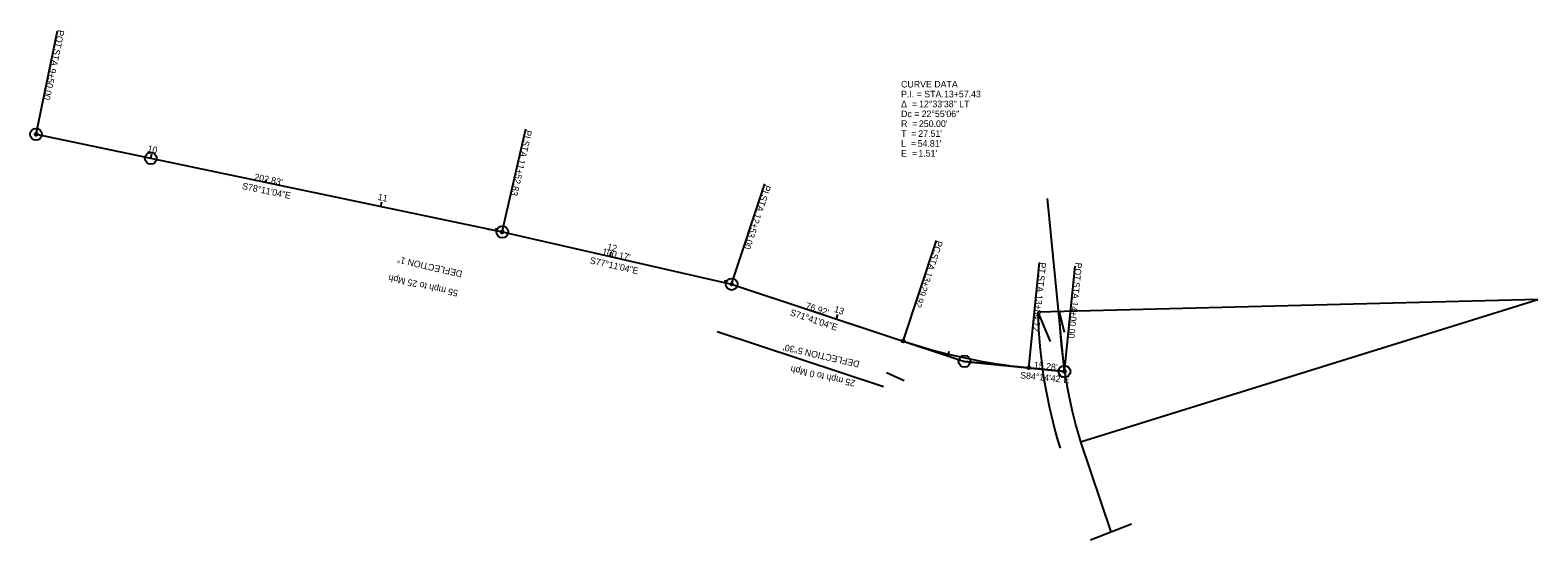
# Model space of a CAD drawing. Extents: x 1815851 to 1817341, y 427933 to 428286.
import ezdxf

# ---------------------------------------------------------------- set-up
doc = ezdxf.new("R2010")
doc.units = 0
for name, color, linetype in [('Default', 7, 'Continuous'), ('DT_P_Graded_Shoulder', 7, 'Continuous'), ('GE_P_Alignment', 7, 'Continuous'), ('GE_P_Alignment_100_Bearings', 7, 'Continuous'), ('GE_P_Alignment_100_Cardinal_Points', 7, 'Continuous'), ('GE_P_Alignment_100_Curve_Data', 7, 'Continuous'), ('GE_P_Alignment_100_Distances', 7, 'Continuous'), ('GE_P_Alignment_100_Stations', 7, 'Continuous'), ('PV_P_EOP', 7, 'Continuous'), ('SC_Scratch1', 7, 'Continuous')]:
    doc.layers.add(name, color=color, linetype=linetype)

msp = doc.modelspace()

# ---------------------------------------------------------------- linework, layer by layer
at = {"layer": 'Default'}
for p, q in [((1817139.41, 428004.77), (1817132.13, 428078.38)), ((1816893.7, 428065.42), (1816894.78, 428065.19)), ((1816900.03, 428064.1), (1816997.7, 428041.88)), ((1816997.7, 428041.88), (1817096.84, 428009.06)), ((1817340.98, 428035.36), (1817128.04, 428030)), ((1817146.28, 427974.88), (1817340.98, 428035.36)), ((1817128.04, 428030), (1817133.33, 428017.48)), ((1817137.17, 428030.23), (1817139.32, 428021.53)), ((1817139.41, 428004.77), (1817096.84, 428009.06)), ((1817146.28, 427974.88), (1817159.22, 427936.56)), ((1817150.53, 427933.17), (1817167.91, 427939.95))]:
    msp.add_line(p, q, dxfattribs=at)
msp.add_circle((1816997.7, 428041.88), 2.5, dxfattribs=at)
for radius in [213.01, 203.88, 203.88]:
    msp.add_arc((1817340.98, 428035.36), radius, 181.44234, 197.25665, dxfattribs=at)
at = {"layer": 'DT_P_Graded_Shoulder'}
for p, q in [((1816991.51, 428021.81), (1817062.3, 427998.38)), ((1817063.63, 428004.29), (1817071.09, 428000.96))]:
    msp.add_line(p, q, dxfattribs=at)
at = {"layer": 'GE_P_Alignment'}
for p, q in [((1816701.49, 428105.63), (1816900.03, 428064.1)), ((1816900.03, 428064.1), (1816997.7, 428041.88)), ((1816997.7, 428041.88), (1817070.72, 428017.71)), ((1817124.21, 428006.3), (1817139.41, 428004.77))]:
    msp.add_line(p, q, dxfattribs=at)
msp.add_arc((1817149.28, 428255.04), 250, 251.68439, 264.245, dxfattribs=at)
at = {"layer": 'GE_P_Alignment_100_Cardinal_Points'}
for p, q in [((1816701.49, 428105.63), (1816710.7, 428149.68)), ((1816900.03, 428064.1), (1816910.01, 428107.98)), ((1816997.7, 428041.88), (1817011.84, 428084.6)), ((1817070.72, 428017.71), (1817084.86, 428060.43)), ((1817124.21, 428006.3), (1817128.72, 428051.08)), ((1817139.41, 428004.77), (1817143.92, 428049.55))]:
    msp.add_line(p, q, dxfattribs=at)
for centre in [(1816701.49, 428105.63), (1816900.03, 428064.1), (1816997.7, 428041.88), (1817070.72, 428017.71), (1817124.21, 428006.3), (1817139.41, 428004.77)]:
    msp.add_circle(centre, 0.6, dxfattribs=at)
at = {"layer": 'GE_P_Alignment_100_Stations'}
for p, q in [((1816701.49, 428105.63), (1816701.73, 428106.81)), ((1816750.43, 428095.39), (1816750.84, 428097.35)), ((1816799.37, 428085.16), (1816799.62, 428086.33)), ((1816848.31, 428074.92), (1816848.72, 428076.88)), ((1816897.25, 428064.68), (1816897.5, 428065.85)), ((1816946.02, 428053.64), (1816946.46, 428055.59)), ((1816994.77, 428042.55), (1816995.04, 428043.72)), ((1817042.32, 428027.11), (1817042.94, 428029.01)), ((1817090.02, 428012.17), (1817090.3, 428013.34))]:
    msp.add_line(p, q, dxfattribs=at)
at = {"layer": 'SC_Scratch1'}
for p, q in [((1816997.7, 428041.88), (1817096.84, 428009.06)), ((1817096.84, 428009.06), (1817139.41, 428004.77))]:
    msp.add_line(p, q, dxfattribs=at)
for centre in [(1816701.49, 428105.63), (1816750.38, 428095.41), (1816900.03, 428064.1), (1817096.84, 428009.06), (1817139.41, 428004.77)]:
    msp.add_circle(centre, 2.5, dxfattribs=at)
msp.add_arc((1817149.28, 428255.04), 250, 251.68439, 264.245, dxfattribs=at)

# ---------------------------------------------------------------- texts
at = {"layer": 'GE_P_Alignment_100_Bearings'}
for s, rotation, p in [('S78°11\'04"E', 348.18439, (1816789.07, 428082.41)), ('S77°11\'04"E', 347.18439, (1816937.13, 428050.74)), ('S71°41\'04"E', 341.68439, (1817022.31, 428028.68)), ('S84°14\'42"E', 354.245, (1817120.45, 428001.86))]:
    msp.add_text(s, height=2.8, rotation=rotation, dxfattribs=at).set_placement(p)
at = {"layer": 'GE_P_Alignment_100_Cardinal_Points'}
for s, rotation, p in [('POT', 258.18439, (1816710.86, 428150.22)), (' STA. ', 258.18439, (1816709.39, 428143.17)), ('9+50.00', 258.18439, (1816707.45, 428133.92)), ('PI', 257.18439, (1816909.98, 428107.68)), (' STA. ', 257.18439, (1816909.23, 428104.37)), ('11+52.83', 257.18439, (1816907.13, 428095.16)), (' STA. ', 251.68439, (1817010.74, 428081.16)), ('PI', 251.68439, (1817011.81, 428084.38)), ('12+53.00', 251.68439, (1817007.77, 428072.18)), ('PC', 251.68439, (1817085, 428060.71)), (' STA. ', 251.68439, (1817083.55, 428056.36)), ('13+29.92', 251.68439, (1817080.58, 428047.38)), ('PT', 264.245, (1817128.79, 428051.29)), ('POT', 264.245, (1817144.13, 428051.22)), (' STA. ', 264.245, (1817128.35, 428046.9)), (' STA. ', 264.245, (1817143.41, 428044.05)), ('13+84.72', 264.245, (1817127.4, 428037.5)), ('14+00.00', 264.245, (1817142.46, 428034.65))]:
    msp.add_text(s, height=2.8, rotation=rotation, dxfattribs=at).set_placement(p)
at = {"layer": 'GE_P_Alignment_100_Curve_Data'}
for s, p in [('CURVE DATA', (1817069.84, 428125.55)), ('P.I. = STA. ', (1817069.84, 428121.35)), ('13+57.43', (1817088.1, 428121.35)), ('Δ  = ', (1817069.84, 428117.15)), ('12°33\'38" LT', (1817077.51, 428117.15)), ('Dc = ', (1817069.84, 428112.95)), ('R  = ', (1817069.84, 428108.75)), ("250.00'", (1817077.42, 428108.75)), ('22°55\'06"', (1817078.58, 428112.95)), ('T  = ', (1817069.84, 428104.55)), ("27.51'", (1817077.17, 428104.55)), ('L  = ', (1817069.84, 428100.35)), ('E  = ', (1817069.84, 428096.15)), ("54.81'", (1817076.88, 428100.35)), ("1.51'", (1817077.18, 428096.15))]:
    msp.add_text(s, height=2.8, dxfattribs=at).set_placement(p)
at = {"layer": 'GE_P_Alignment_100_Distances'}
for s, rotation, p in [("202.83'", 348.18439, (1816794.23, 428086.28)), ("100.17'", 347.18439, (1816942.36, 428054.51)), ("76.92'", 341.68439, (1817028.94, 428031.58)), ("15.28'", 354.245, (1817126.28, 428006.14))]:
    msp.add_text(s, height=2.8, rotation=rotation, dxfattribs=at).set_placement(p)
at = {"layer": 'GE_P_Alignment_100_Stations'}
for s, rotation, p in [('10', 348.18439, (1816748.76, 428098.3)), ('11', 348.18439, (1816846.83, 428077.78)), ('12', 347.18439, (1816944.46, 428056.56)), ('13', 341.68439, (1817041.06, 428030.16))]:
    msp.add_text(s, height=2.8, rotation=rotation, dxfattribs=at).set_placement(p)
at = {"layer": 'PV_P_EOP'}
for s, p in [('DEFLECTION 1°', (1816883.2, 428047.48)), ('55 mph to 25 Mph', (1816881.34, 428039.29)), ("DEFLECTION 5°30'", (1817052.37, 428009.13)), ('25 mph to 0 Mph', (1817050.51, 428000.94))]:
    msp.add_text(s, height=2.8, rotation=167.18439, dxfattribs=at).set_placement(p)

doc.saveas('drawing.dxf')
